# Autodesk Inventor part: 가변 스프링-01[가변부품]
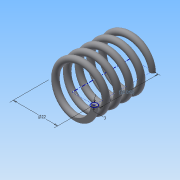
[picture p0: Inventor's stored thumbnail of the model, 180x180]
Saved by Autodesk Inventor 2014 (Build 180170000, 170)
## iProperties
Created: 2015-09
Part Number: 가변 스프링-01[가변부품]
Material: 강철, 탄소
Document SubType Name: Modeling
Designer: study
Density: 7.87 g/cm^3
Appearance: 반연마
Mass: 18.7976 g
Surface Area: 32.4648 cm^2
Volume: 2.38851 cm^3
Author: study
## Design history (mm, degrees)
sketch "스케치1"
  geometry: L1 (0, 0)-(11, 0); L2 (11, 0)-(11, 29.043); L3 (11, 29.043)-(0, 29.043); L4 (0, 29.043)-(0, 0); C1 r 1.5 at (11, 0)
  constraints: 8 end point, 2 parallel, 1 centre point, 1 coincident, 1 horizontal, 1 perpendicular
  dimensions: "d0" = 22 diameter of L2 L4; "d1" = 29.04259 distance of L1.end L2.end (derived); "d2" = 3 diameter of C1
feature "코일1" sketch "스케치1" pitch "d3" = 10; turns "d5" = 5; dims "d4" = 29.04259 (= d1), "d6" = 0, angle "d7" = 90 deg, angle "d8" = 90 deg, "d9" = 0, "d10" = 0
node "작업 평면1"
sketch "스케치2"
  geometry: L1 (-12.5, 0)-(-9.5, 0) reference; L2 (-12.5, 0)-(-9.5, 0) reference; 1 further point
  constraints: 2 horizontal alignment
extrude "돌출1" cut sketch "스케치2" stored distance "d12" = 10; taper "d13" = 0 deg
node "작업 평면2"
sketch "스케치3"
  geometry: L1 (-9.5, 0)-(-12.5, 0) reference; 1 further point
  constraints: 1 horizontal alignment
extrude "돌출2" cut sketch "스케치3" stored distance "d15" = 10; taper "d16" = 0 deg
node "솔리드1"
node "절단 모서리 투영1"
node "절단 모서리 투영2"
node "절단 모서리 투영3"
other parameters: "d11" = 0, "d14" = 29.04259 (= d1)
